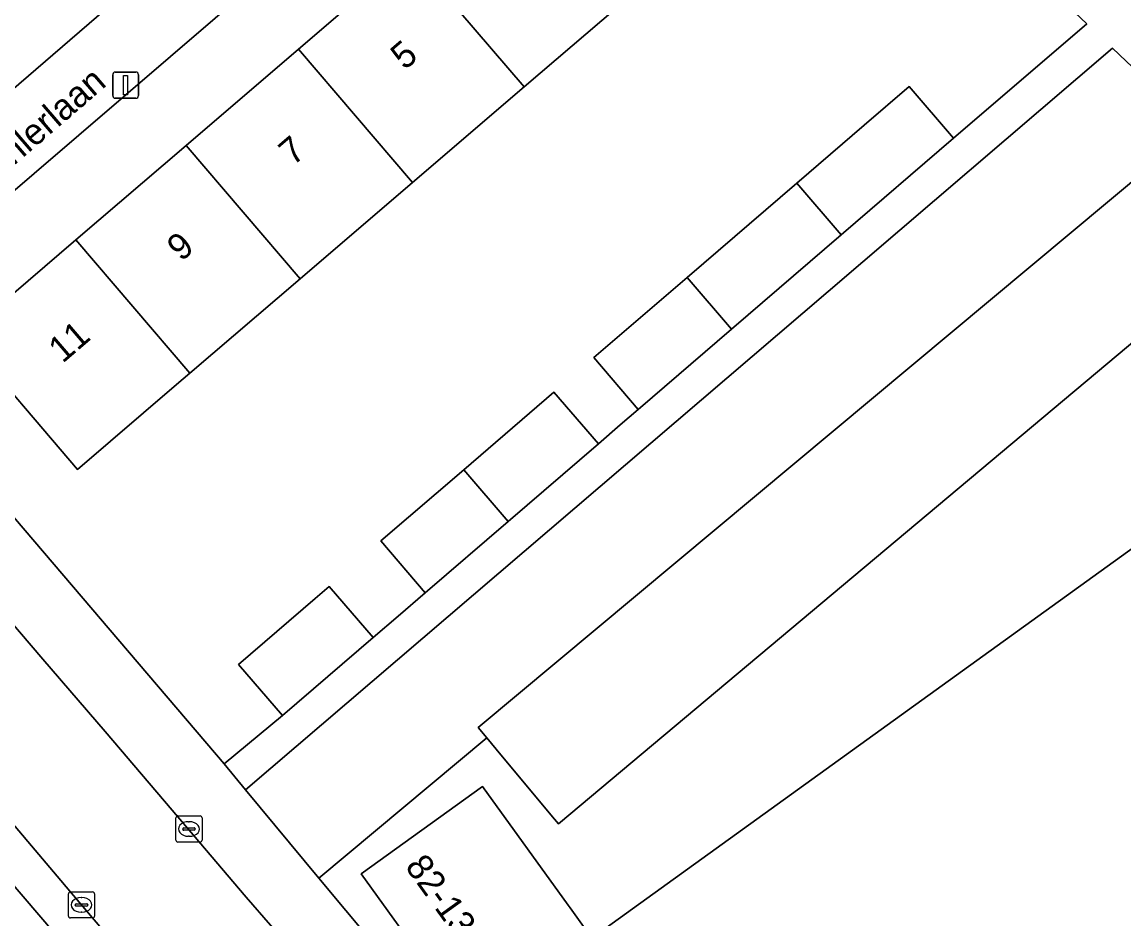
# Model space of a CAD drawing. Extents: x 159039 to 160102, y 381214 to 382524.
# Drawn here: x 159387.61 to 159429.85, y 381492.82 to 381527.19 of the extents above; entities that cross this region are included whole.
import ezdxf

# ---------------------------------------------------------------- set-up
doc = ezdxf.new("R2010")
doc.units = 0
for name, color, linetype in [('IMGEO_Erf', 7, 'Continuous'), ('IMGEO_Groenvoorziening', 7, 'Continuous'), ('IMGEO_Kolk', 7, 'Continuous'), ('IMGEO_Lichtmast', 7, 'Continuous'), ('IMGEO_Openbare_ruimte_label', 7, 'Continuous'), ('IMGEO_Pand', 7, 'Continuous'), ('IMGEO_Pand_nummerreeks', 7, 'Continuous'), ('IMGEO_Parkeervlak_halfverhard', 7, 'Continuous'), ('IMGEO_Rijbaan_lokaal_halfverhard', 7, 'Continuous'), ('IMGEO_Rijbaan_lokaal_open', 7, 'Continuous'), ('IMGEO_Voetpad_open', 7, 'Continuous')]:
    doc.layers.add(name, color=color, linetype=linetype)

msp = doc.modelspace()

# ---------------------------------------------------------------- linework, layer by layer
at = {"layer": 'IMGEO_Erf'}
for points in [[(159413.114, 381517.408), (159417.312, 381521.019), (159419.893, 381523.238), (159421.617, 381524.72), (159423.321, 381522.739), (159428.428, 381527.13), (159419.794, 381535.294), (159412.409, 381542.277), (159381.123, 381515.43), (159395.359, 381498.763), (159397.592, 381500.614), (159395.909, 381502.571), (159398.849, 381505.099), (159399.391, 381505.565), (159401.07, 381503.604), (159402.027, 381504.427), (159403.069, 381505.323), (159401.369, 381507.308), (159404.544, 381510.038), (159408.005, 381513.015), (159409.705, 381511.03), (159410.544, 381511.751), (159411.238, 381512.348), (159409.538, 381514.333)], [(159394.051, 381513.737), (159393.538, 381513.297), (159389.74, 381510.044), (159385.364, 381515.152), (159389.675, 381518.845), (159393.899, 381522.464), (159398.206, 381526.153), (159402.482, 381529.816), (159406.688, 381533.42), (159411.07, 381537.173), (159414.323, 381533.376), (159415.446, 381532.066), (159411.064, 381528.312), (159406.858, 381524.709), (159402.582, 381521.045), (159398.275, 381517.356)]]:
    msp.add_lwpolyline(points, close=True, dxfattribs=at)
for points in [[(159361.794, 381538.002), (159379.202, 381517.668), (159392.797, 381529.398)], [(159374.118, 381500), (159375.936, 381501.558), (159377.269, 381500), (159379.626, 381497.246), (159383.349, 381492.893), (159386.93, 381488.708), (159390.522, 381484.51), (159394.307, 381480.086), (159397.979, 381475.794), (159400.855, 381478.267), (159400.885, 381478.302), (159397.195, 381482.524), (159382.243, 381500), (159379.225, 381503.503)]]:
    msp.add_lwpolyline(points, dxfattribs=at)
at = {"layer": 'IMGEO_Groenvoorziening'}
msp.add_lwpolyline([(159435.656, 381519.493), (159408.178, 381496.463), (159408.027, 381496.644), (159405.971, 381499.107), (159405.429, 381499.757), (159398.993, 381494.387), (159408.491, 381483.004), (159408.785, 381483.207), (159400.619, 381494.55), (159405.27, 381497.898), (159408.548, 381493.351), (159408.621, 381493.25), (159409.461, 381492.085), (159437.641, 381512.413)], dxfattribs=at)
at = {"layer": 'IMGEO_Kolk'}
for p, q in [((159393.587, 381496.769), (159394.439, 381496.769)), ((159393.512, 381495.843), (159393.512, 381496.695)), ((159393.814, 381496.312), (159394.212, 381496.312)), ((159394, 381496.549), (159394.025, 381496.549)), ((159394.513, 381496.695), (159394.513, 381495.843)), ((159393.771, 381496.263), (159393.771, 381496.275)), ((159394.209, 381496.226), (159393.811, 381496.226)), ((159394.023, 381495.989), (159393.998, 381495.989)), ((159394.255, 381496.275), (159394.255, 381496.263)), ((159394.439, 381495.769), (159393.587, 381495.769)), ((159389.392, 381492.934), (159389.392, 381493.786)), ((159389.467, 381493.86), (159390.319, 381493.86)), ((159390.393, 381493.786), (159390.393, 381492.934)), ((159389.651, 381493.354), (159389.651, 381493.366)), ((159389.694, 381493.403), (159390.092, 381493.403)), ((159389.88, 381493.64), (159389.905, 381493.64)), ((159390.135, 381493.366), (159390.135, 381493.354)), ((159390.089, 381493.317), (159389.691, 381493.317)), ((159389.903, 381493.08), (159389.878, 381493.08)), ((159390.319, 381492.86), (159389.467, 381492.86))]:
    msp.add_line(p, q, dxfattribs=at)
for points in [[(159393.587, 381496.769), (159394.439, 381496.769)], [(159393.512, 381495.843), (159393.512, 381496.695)], [(159394.513, 381496.695), (159394.513, 381495.843)], [(159394.439, 381495.769), (159393.587, 381495.769)], [(159389.392, 381492.934), (159389.392, 381493.786)], [(159389.467, 381493.86), (159390.319, 381493.86)], [(159390.393, 381493.786), (159390.393, 381492.934)], [(159390.319, 381492.86), (159389.467, 381492.86)]]:
    msp.add_lwpolyline(points, dxfattribs=at)
for centre, radius, start, end in [((159393.589, 381496.693), 0.0765, 91.552, 178.448), ((159393.589, 381496.693), 0.0765, 91.552, 178.448), ((159394.437, 381496.693), 0.0765, 1.552, 88.448), ((159394.437, 381496.693), 0.0765, 1.552, 88.448), ((159393.811, 381496.272), 0.0403, 85.8775, 175.7526), ((159394.216, 381496.274), 0.0386, 1.7309, 96.639), ((159393.808, 381496.262), 0.0366, 178.938, 274.7102), ((159394.212, 381496.269), 0.043, 264.8664, 352.4533), ((159393.589, 381495.845), 0.0765, 181.552, 268.448), ((159393.589, 381495.845), 0.0765, 181.552, 268.448), ((159394.437, 381495.845), 0.0765, 271.552, 358.448), ((159394.437, 381495.845), 0.0765, 271.552, 358.448), ((159389.469, 381493.784), 0.0765, 91.552, 178.448), ((159389.469, 381493.784), 0.0765, 91.552, 178.448), ((159390.317, 381493.784), 0.0765, 1.552, 88.448), ((159390.317, 381493.784), 0.0765, 1.552, 88.448), ((159389.691, 381493.363), 0.0403, 85.8775, 175.7526), ((159389.688, 381493.353), 0.0366, 178.938, 274.7102), ((159390.092, 381493.36), 0.043, 264.8664, 352.4533), ((159390.096, 381493.365), 0.0386, 1.7309, 96.639), ((159389.469, 381492.936), 0.0765, 181.552, 268.448), ((159389.469, 381492.936), 0.0765, 181.552, 268.448), ((159390.317, 381492.936), 0.0765, 271.552, 358.448), ((159390.317, 381492.936), 0.0765, 271.552, 358.448)]:
    msp.add_arc(centre, radius, start, end, dxfattribs=at)
for centre, major_axis, ratio, start_param, end_param in [((159393.999, 381496.269), (-0.387, 0.002), 0.722429, 4.712389, 7.853982), ((159394.024, 381496.269), (-0.39, 0.002), 0.717154, 1.570796, 4.712389), ((159389.879, 381493.36), (-0.387, 0.002), 0.722429, 4.712389, 7.853982), ((159389.904, 381493.36), (-0.39, 0.002), 0.717154, 1.570796, 4.712389)]:
    msp.add_ellipse(centre, major_axis=major_axis, ratio=ratio, start_param=start_param, end_param=end_param, dxfattribs=at)
at = {"layer": 'IMGEO_Lichtmast'}
for p, q in [((159391.088, 381524.374), (159391.088, 381525.174)), ((159391.088, 381525.174), (159391.088, 381524.374)), ((159391.188, 381525.274), (159391.978, 381525.274)), ((159391.978, 381525.274), (159391.188, 381525.274)), ((159392.078, 381525.174), (159392.078, 381524.374)), ((159392.078, 381524.374), (159392.078, 381525.174)), ((159391.978, 381524.274), (159391.188, 381524.274)), ((159391.188, 381524.274), (159391.978, 381524.274))]:
    msp.add_line(p, q, dxfattribs=at)
msp.add_lwpolyline([(159391.508, 381525.149), (159391.658, 381525.149), (159391.658, 381524.399), (159391.508, 381524.399), (159391.508, 381525.149)], dxfattribs=at)
for centre, start, end in [((159391.188, 381525.174), 90, 180), ((159391.188, 381525.174), 90, 180), ((159391.978, 381525.174), 0, 90), ((159391.978, 381525.174), 360, 90), ((159391.188, 381524.374), 180, 270), ((159391.188, 381524.374), 180, 270), ((159391.978, 381524.374), 270, 0), ((159391.978, 381524.374), 270, 0)]:
    msp.add_arc(centre, 0.1, start, end, dxfattribs=at)
at = {"layer": 'IMGEO_Pand'}
for points in [[(159411.064, 381528.312), (159406.688, 381533.42), (159402.482, 381529.816), (159406.858, 381524.709)], [(159402.582, 381521.045), (159406.858, 381524.709), (159402.482, 381529.816), (159398.206, 381526.153)], [(159393.899, 381522.464), (159398.275, 381517.356), (159402.582, 381521.045), (159398.206, 381526.153)], [(159423.321, 381522.739), (159421.617, 381524.72), (159419.893, 381523.238), (159417.312, 381521.019), (159419.012, 381519.034)], [(159393.899, 381522.464), (159389.675, 381518.845), (159394.051, 381513.737), (159398.275, 381517.356)], [(159413.114, 381517.408), (159414.814, 381515.424), (159419.012, 381519.034), (159417.312, 381521.019)], [(159394.051, 381513.737), (159389.675, 381518.845), (159385.364, 381515.152), (159389.74, 381510.044), (159393.538, 381513.297)], [(159414.814, 381515.424), (159413.114, 381517.408), (159409.538, 381514.333), (159411.238, 381512.348)], [(159443.672, 381502.214), (159445.674, 381503.658), (159438.771, 381513.228), (159437.641, 381512.413), (159409.461, 381492.085), (159408.621, 381493.25), (159408.548, 381493.351), (159405.27, 381497.898), (159400.619, 381494.55), (159408.785, 381483.207), (159410.617, 381484.502), (159411.698, 381483.002), (159413.525, 381480.468), (159429.891, 381492.273)], [(159409.705, 381511.03), (159408.005, 381513.015), (159404.544, 381510.038), (159406.244, 381508.054)], [(159406.244, 381508.054), (159404.544, 381510.038), (159401.369, 381507.308), (159403.069, 381505.323)], [(159398.849, 381505.099), (159395.909, 381502.571), (159397.592, 381500.614), (159401.07, 381503.604), (159399.391, 381505.565)]]:
    msp.add_lwpolyline(points, close=True, dxfattribs=at)
at = {"layer": 'IMGEO_Parkeervlak_halfverhard'}
msp.add_lwpolyline([(159435.656, 381519.493), (159435.016, 381520.142), (159432.318, 381522.873), (159405.096, 381500.156), (159405.429, 381499.757), (159405.971, 381499.107), (159408.027, 381496.644), (159408.178, 381496.463)], close=True, dxfattribs=at)
at = {"layer": 'IMGEO_Rijbaan_lokaal_halfverhard'}
msp.add_lwpolyline([(159432.318, 381522.873), (159432.643, 381523.144), (159429.94, 381525.7), (159429.42, 381526.192), (159418.516, 381516.866), (159396.185, 381497.766), (159398.993, 381494.387), (159405.429, 381499.757), (159405.096, 381500.156)], close=True, dxfattribs=at)
at = {"layer": 'IMGEO_Rijbaan_lokaal_open'}
for points in [[(159412.409, 381542.277), (159413.662, 381543.353), (159428.908, 381556.436), (159429.817, 381557.352), (159427.555, 381559.41), (159424.658, 381556.679), (159424.489, 381556.52), (159424.271, 381556.333), (159411.874, 381545.767), (159410.352, 381544.44), (159400.002, 381535.554), (159398.155, 381533.97), (159392.797, 381529.398), (159379.202, 381517.668), (159381.123, 381515.43)], [(159379.3, 381513.434), (159376.8, 381516.357), (159376.214, 381517.042), (159361.379, 381534.296), (159359.079, 381537.039), (159355.206, 381533.839), (159359.018, 381529.42), (159359.717, 381528.593), (159370.22, 381516.331), (159380.301, 381504.635), (159381.439, 381503.315), (159384.255, 381500), (159389.868, 381493.391), (159392.642, 381490.134), (159401.023, 381480.383), (159401.74, 381479.524), (159405.572, 381482.813), (159404.878, 381483.645), (159398.069, 381491.509), (159396.211, 381493.655), (159394.17, 381496.049), (159390.802, 381500), (159388.415, 381502.775)]]:
    msp.add_lwpolyline(points, close=True, dxfattribs=at)
at = {"layer": 'IMGEO_Voetpad_open'}
for points in [[(159419.794, 381535.294), (159428.428, 381527.13), (159423.321, 381522.739), (159419.012, 381519.034), (159414.814, 381515.424), (159411.238, 381512.348), (159410.544, 381511.751), (159409.705, 381511.03), (159406.244, 381508.054), (159403.069, 381505.323), (159402.027, 381504.427), (159401.07, 381503.604), (159397.592, 381500.614), (159395.359, 381498.763), (159396.185, 381497.766), (159418.516, 381516.866), (159429.42, 381526.192), (159429.94, 381525.7)], [(159379.3, 381513.434), (159388.415, 381502.775), (159390.802, 381500), (159394.17, 381496.049), (159396.211, 381493.655), (159398.069, 381491.509), (159404.878, 381483.645), (159405.572, 381482.813), (159415.578, 381471.202), (159418.061, 381472.201), (159409.67, 381481.596), (159409.881, 381481.754), (159410.381, 381482.105), (159411.698, 381483.002), (159410.617, 381484.502), (159408.785, 381483.207), (159408.491, 381483.004), (159398.993, 381494.387), (159396.185, 381497.766), (159395.359, 381498.763), (159381.123, 381515.43)], [(159379.225, 381503.503), (159382.243, 381500), (159397.195, 381482.524), (159400.885, 381478.302), (159402.03, 381476.877), (159410.608, 381466.883), (159411.724, 381467.861), (159401.74, 381479.524), (159401.023, 381480.383), (159392.642, 381490.134), (159389.868, 381493.391), (159384.255, 381500), (159381.439, 381503.315), (159380.301, 381504.635)]]:
    msp.add_lwpolyline(points, dxfattribs=at)

# ---------------------------------------------------------------- texts
at = {"layer": 'IMGEO_Openbare_ruimte_label'}
msp.add_text('Mahlerlaan', height=1, rotation=40.7442, dxfattribs=at).set_placement((159385.887, 381520.465))
at = {"layer": 'IMGEO_Pand_nummerreeks'}
for s, rotation, p in [('5', 40.585, (159402.284, 381525.327)), ('7', 40.585, (159398, 381521.657)), ('9', 40.585, (159393.715, 381517.987)), ('11', 40.585, (159389.168, 381514.092)), ('82-130', 305.7524, (159402.268, 381494.827))]:
    msp.add_text(s, height=1, rotation=rotation, dxfattribs=at).set_placement(p)

doc.saveas('drawing.dxf')
